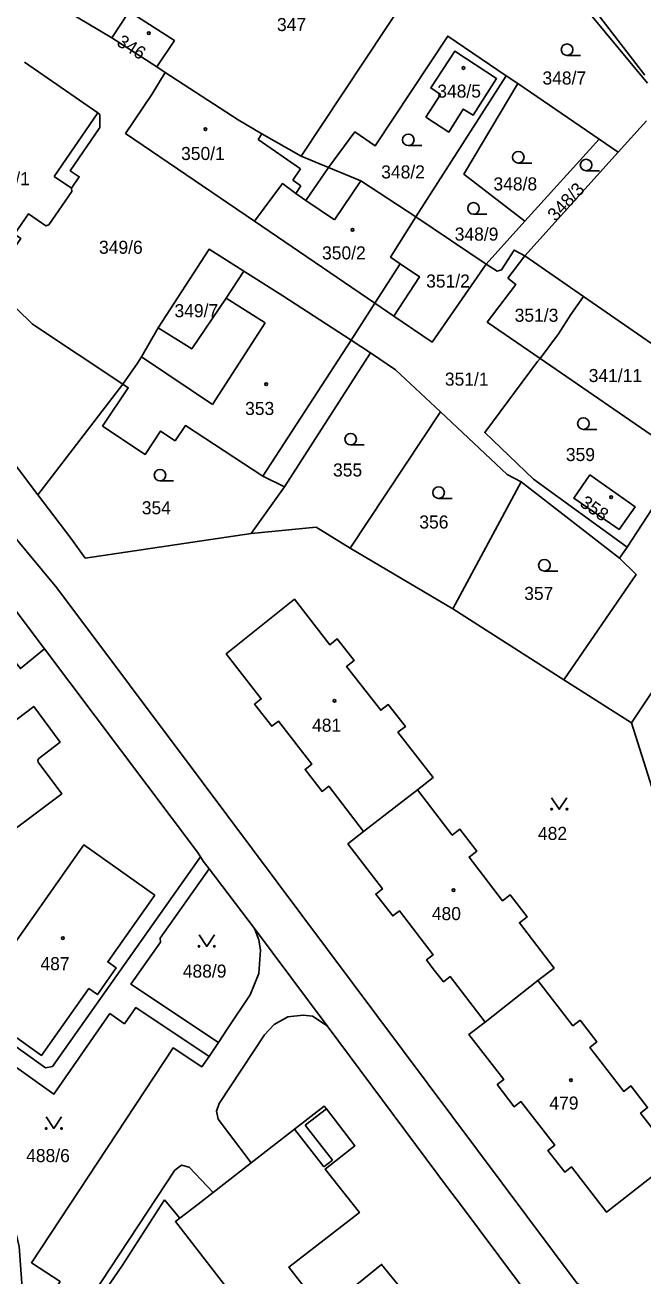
# Model space of a CAD drawing. Extents: x -558358 to -557517, y -1073785 to -1073189.
# Drawn here: x -557990.2 to -557909.7, y -1073433.5 to -1073270.7 of the extents above; entities that cross this region are included whole.
import ezdxf

# ---------------------------------------------------------------- set-up
doc = ezdxf.new("R2010")
doc.units = 0
for name, color, linetype in [('Hranice parcel', 7, 'Continuous'), ('Parcelní čísla', 7, 'Continuous'), ('Vnitřní kresba', 7, 'Continuous'), ('Značky budov', 7, 'Continuous'), ('Značky kultur', 7, 'Continuous')]:
    doc.layers.add(name, color=color, linetype=linetype)

msp = doc.modelspace()

# ---------------------------------------------------------------- linework, layer by layer
at = {"layer": 'Hranice parcel'}
for p, q in [((-557909.08, -1073278.25), (-557930.32, -1073252.64)), ((-557954.2, -1073287.72), (-557935.78, -1073259.94)), ((-557988.45, -1073266.61), (-557978.88, -1073272.32)), ((-557978.88, -1073272.32), (-557973.02, -1073276.12)), ((-557973.02, -1073276.12), (-557971.93, -1073276.83)), ((-557939.28, -1073295.66), (-557927.49, -1073277.3)), ((-557927.49, -1073277.3), (-557926.01, -1073278.28)), ((-557926.01, -1073278.28), (-557915.41, -1073285.51)), ((-557912.91, -1073287.22), (-557909.23, -1073283.14)), ((-557915.41, -1073285.51), (-557925.06, -1073296.21)), ((-557912.91, -1073287.22), (-557915.41, -1073285.51)), ((-557950.63, -1073289.21), (-557954.2, -1073287.72)), ((-557925.08, -1073300.71), (-557912.91, -1073287.22)), ((-557930.1, -1073301.79), (-557939.28, -1073295.66)), ((-557960.27, -1073296.22), (-557944.6, -1073306.89)), ((-557925.06, -1073296.21), (-557930.1, -1073301.79)), ((-557927.31, -1073303.62), (-557925.08, -1073300.71)), ((-557917.44, -1073306), (-557925.08, -1073300.71)), ((-557944.6, -1073306.89), (-557947.68, -1073311.68)), ((-557944.6, -1073306.89), (-557942.12, -1073308.58)), ((-557923.1, -1073314.09), (-557930, -1073309.35)), ((-557945.18, -1073313.34), (-557947.68, -1073311.68)), ((-557956.39, -1073330.78), (-557945.18, -1073313.34)), ((-557923.1, -1073314.09), (-557906.54, -1073325.46)), ((-557988.49, -1073331.84), (-557977.43, -1073317.43)), ((-557947.81, -1073338.78), (-557936.06, -1073321.05)), ((-557911.75, -1073338.65), (-557904.1, -1073326.9)), ((-557960.73, -1073336.87), (-557956.39, -1073330.78)), ((-557934.44, -1073346.66), (-557925.54, -1073330.14)), ((-557912.73, -1073340.1), (-557925.54, -1073330.14)), ((-557911.2, -1073361.51), (-557892.99, -1073334.25)), ((-557947.81, -1073338.78), (-557934.44, -1073346.66)), ((-557911.75, -1073338.65), (-557912.73, -1073340.1)), ((-557934.44, -1073346.66), (-557919.99, -1073355.94)), ((-557919.99, -1073355.94), (-557911.2, -1073361.51)), ((-557911.2, -1073361.51), (-557908.52, -1073369.92)), ((-557939.06, -1073370.25), (-557946.07, -1073375.66)), ((-557967.34, -1073378.97), (-557986.61, -1073406.29)), ((-557972.56, -1073389.56), (-557966.21, -1073380.53)), ((-557966.21, -1073380.53), (-557960.31, -1073388.29)), ((-557960.31, -1073388.29), (-557950.81, -1073400.97)), ((-557960.31, -1073388.29), (-557959.73, -1073389.78)), ((-557923.37, -1073395.09), (-557930.26, -1073400.48)), ((-557950.81, -1073400.97), (-557952.73, -1073399.73)), ((-557966.19, -1073404.96), (-557964.99, -1073403.16)), ((-557965.04, -1073413.14), (-557960.73, -1073418.81)), ((-557965.67, -1073422.67), (-557968.81, -1073419.39)), ((-557960.73, -1073418.81), (-557965.67, -1073422.67)), ((-557970.03, -1073426.04), (-557971.99, -1073423.64))]:
    msp.add_line(p, q, dxfattribs=at)
for points in [[(-557930.24, -1073250.53), (-557916.49, -1073268.06), (-557909.46, -1073277.19)], [(-557973.02, -1073276.12), (-557970.72, -1073272.68), (-557976.62, -1073268.9), (-557978.88, -1073272.32)], [(-557992.18, -1073271.14), (-558017.7, -1073308.66), (-558015.75, -1073309.85), (-558004.08, -1073317.8), (-557996.67, -1073322.48), (-557993.43, -1073325.31), (-557988.49, -1073331.84)], [(-557927.49, -1073277.3), (-557935.12, -1073272.11), (-557944.58, -1073286.41), (-557947.22, -1073284.58), (-557950.63, -1073289.21)], [(-557937.99, -1073282.67), (-557936.08, -1073279.73), (-557937.34, -1073278.85), (-557934.2, -1073274.07), (-557928.77, -1073277.64), (-557931.8, -1073282.4), (-557933.09, -1073281.6), (-557934.98, -1073284.6), (-557937.99, -1073282.67)], [(-557995.47, -1073303.55), (-557992.42, -1073299.14), (-557991.6, -1073299.71), (-557990.74, -1073298.46), (-557991.57, -1073297.9), (-557989.74, -1073295.26), (-557987.45, -1073296.82), (-557987.09, -1073296.7), (-557984.08, -1073292.32), (-557984.13, -1073291.92), (-557983.12, -1073290.42), (-557984.28, -1073289.64), (-557980.42, -1073284.02), (-557980.45, -1073282.32), (-557980.68, -1073282.11), (-557990.25, -1073275.48)], [(-557971.93, -1073276.83), (-557973.65, -1073279.73), (-557977.09, -1073284.77), (-557960.27, -1073296.22)], [(-557971.93, -1073276.83), (-557962.4, -1073283.03), (-557959.33, -1073284.84), (-557954.2, -1073287.72)], [(-557926.01, -1073278.28), (-557933.02, -1073290.08), (-557925.06, -1073296.21)], [(-557960.27, -1073296.22), (-557956.66, -1073291.3), (-557954.92, -1073292.62), (-557953.6, -1073293.52), (-557950.63, -1073289.21)], [(-557950.63, -1073289.21), (-557946.45, -1073290.96), (-557939.28, -1073295.66)], [(-557942.12, -1073308.58), (-557938.8, -1073303.44), (-557941.3, -1073301.76), (-557942.56, -1073300.91), (-557939.28, -1073295.66)], [(-557972.83, -1073310.08), (-557966.21, -1073299.85), (-557961.67, -1073302.72)], [(-557930.1, -1073301.79), (-557928.7, -1073302.72), (-557928.1, -1073302.55), (-557926.47, -1073299.96), (-557925.08, -1073300.71)], [(-557942.12, -1073308.58), (-557937.16, -1073311.96), (-557930.1, -1073301.79)], [(-557977.43, -1073317.43), (-557989.2, -1073309.62), (-557995.47, -1073303.55)], [(-557961.67, -1073302.72), (-557963.96, -1073306.23), (-557968.46, -1073312.83), (-557972.83, -1073310.08)], [(-557947.68, -1073311.68), (-557956.58, -1073305.91), (-557961.67, -1073302.72)], [(-557930, -1073309.35), (-557926.23, -1073304.45), (-557927.31, -1073303.62)], [(-557917.44, -1073306), (-557919.08, -1073308.35), (-557920.7, -1073310.88), (-557923.1, -1073314.09)], [(-557906.54, -1073325.46), (-557900.99, -1073317.38), (-557917.44, -1073306)], [(-557972.83, -1073310.08), (-557975.02, -1073313.87), (-557975.51, -1073314.71), (-557977.43, -1073317.43)], [(-558022.09, -1073311.21), (-558020.08, -1073313.87), (-558000.41, -1073328.2), (-557993.92, -1073334.5), (-557986.04, -1073343.93), (-557967.1, -1073369.2), (-557918.24, -1073434.51), (-557914.64, -1073436.24), (-557909.55, -1073436.22), (-557905.05, -1073434.1), (-557902.57, -1073430.65), (-557891.22, -1073414.37), (-557877.97, -1073395.43)], [(-557936.06, -1073321.05), (-557941.93, -1073315.57), (-557945.18, -1073313.34)], [(-557923.1, -1073314.09), (-557923.42, -1073314.47), (-557930.3, -1073323.72), (-557923.97, -1073329.78), (-557911.75, -1073338.65)], [(-557977.43, -1073317.43), (-557976.74, -1073317.89), (-557980.07, -1073322.91)], [(-557925.54, -1073330.14), (-557927.37, -1073329.18), (-557936.06, -1073321.05)], [(-557980.07, -1073322.91), (-557974.55, -1073326.57), (-557972.53, -1073323.54), (-557970.61, -1073324.82)], [(-557970.61, -1073324.82), (-557969.28, -1073322.81), (-557959.2, -1073329.4), (-557956.39, -1073330.78)], [(-557916.62, -1073329.24), (-557918.71, -1073332.26), (-557912.81, -1073336.33), (-557910.69, -1073333.4), (-557916.62, -1073329.24)], [(-557988.49, -1073331.84), (-557984.2, -1073337.5), (-557982.34, -1073340.07), (-557960.73, -1073336.87)], [(-557960.73, -1073336.87), (-557952.24, -1073336.05), (-557947.81, -1073338.78)], [(-557919.99, -1073355.94), (-557910.58, -1073342.2), (-557912.73, -1073340.1)], [(-557987.64, -1073351.9), (-557990.77, -1073354.47), (-557995.82, -1073348.28), (-557992.92, -1073345.89)], [(-557992.92, -1073345.89), (-557991.47, -1073346.8), (-557987.64, -1073351.9)], [(-557939.06, -1073370.25), (-557937.03, -1073368.65), (-557941.61, -1073362.76), (-557940.64, -1073362.01), (-557942.87, -1073359.14), (-557943.85, -1073359.89), (-557948.29, -1073354.18), (-557947.32, -1073353.42), (-557949.52, -1073350.59), (-557950.49, -1073351.35), (-557955.09, -1073345.44), (-557963.96, -1073352.54), (-557959.4, -1073358.42), (-557960.27, -1073359.1), (-557958.05, -1073361.97), (-557957.18, -1073361.3), (-557952.83, -1073366.91), (-557953.7, -1073367.59), (-557951.48, -1073370.46), (-557950.61, -1073369.79), (-557946.07, -1073375.66)], [(-557987.64, -1073351.9), (-557967.72, -1073378.38), (-557967.34, -1073378.97)], [(-558015.07, -1073378.83), (-558009.7, -1073374.87), (-558009.55, -1073374.62), (-558009.63, -1073374.36), (-558012.72, -1073370.26), (-557996.07, -1073357.8), (-557992.97, -1073361.92), (-557992.74, -1073362.04), (-557992.48, -1073361.98), (-557989.05, -1073359.38), (-557985.61, -1073364.04), (-557988.36, -1073366.15), (-557988.52, -1073366.38), (-557988.48, -1073366.66), (-557985.4, -1073370.76), (-558002.63, -1073383.68), (-558005.71, -1073379.56), (-558005.98, -1073379.48), (-558006.26, -1073379.51), (-558009.96, -1073382.24), (-558012.37, -1073378.99), (-558013.71, -1073380.01)], [(-557923.37, -1073395.09), (-557921.26, -1073393.45), (-557925.78, -1073387.56), (-557924.79, -1073386.8), (-557926.98, -1073383.94), (-557927.98, -1073384.7), (-557932.34, -1073379.01), (-557931.35, -1073378.25), (-557933.54, -1073375.39), (-557934.53, -1073376.15), (-557939.06, -1073370.25)], [(-557946.07, -1073375.66), (-557948.14, -1073377.29), (-557943.62, -1073383.15), (-557944.49, -1073383.82), (-557942.29, -1073386.67), (-557941.42, -1073386), (-557937, -1073391.73), (-557937.87, -1073392.4), (-557937.04, -1073393.49), (-557935.69, -1073395.23), (-557934.82, -1073394.56), (-557930.26, -1073400.48)], [(-557973.25, -1073383.95), (-557982.53, -1073377.43), (-557997.25, -1073398.28), (-557988.03, -1073404.82), (-557981.86, -1073396.11), (-557980.74, -1073396.9), (-557978.29, -1073393.44), (-557979.41, -1073392.65), (-557973.25, -1073383.95)], [(-557967.34, -1073378.97), (-557966.98, -1073379.52), (-557966.21, -1073380.53)], [(-557986.61, -1073406.29), (-557987.5, -1073406.44), (-558001.47, -1073396.48), (-558002.38, -1073393.7), (-558003.7, -1073390.42), (-558005.05, -1073388.34), (-558008.08, -1073385.35), (-558013.71, -1073380.01)], [(-557964.99, -1073403.16), (-557976.4, -1073395.54), (-557972.54, -1073390.07), (-557972.56, -1073389.56)], [(-557959.73, -1073389.78), (-557959.52, -1073391.14), (-557959.72, -1073394.15), (-557960.86, -1073396.95), (-557963.76, -1073401.26), (-557964.99, -1073403.16)], [(-557930.26, -1073400.48), (-557932.35, -1073402.1), (-557927.81, -1073407.96), (-557928.68, -1073408.63), (-557926.46, -1073411.51), (-557925.59, -1073410.83), (-557921.19, -1073416.52), (-557922.06, -1073417.2), (-557919.87, -1073420.02), (-557919, -1073419.35), (-557914.46, -1073425.22), (-557905.47, -1073418.2), (-557910.01, -1073412.34), (-557909.08, -1073411.62), (-557911.27, -1073408.79), (-557912.2, -1073409.51), (-557916.62, -1073403.8), (-557915.7, -1073403.08), (-557917.89, -1073400.24), (-557918.82, -1073400.96), (-557923.37, -1073395.09)], [(-557990.11, -1073441.11), (-557990.95, -1073429.72), (-557991.6, -1073426.99), (-558000.34, -1073399.97), (-557986.42, -1073409.86), (-557979.13, -1073399.38), (-557977.23, -1073400.7), (-557975.75, -1073398.59), (-557966.19, -1073404.96)], [(-557952.73, -1073399.73), (-557953.94, -1073399.59), (-557955.93, -1073399.82), (-557957.72, -1073400.8), (-557958.97, -1073402.15), (-557964.89, -1073411.09), (-557965.23, -1073412.1), (-557965.04, -1073413.14)], [(-557943.74, -1073483.99), (-557922.57, -1073454.37), (-557920.54, -1073448.62), (-557920.67, -1073443.5), (-557923.32, -1073437.76), (-557933.57, -1073424.07), (-557935, -1073422.19), (-557950.81, -1073400.97)], [(-557966.19, -1073404.96), (-557967.15, -1073406.3), (-557970.9, -1073403.86), (-557989.34, -1073431.82), (-557985.62, -1073434.28), (-557990.11, -1073441.11)], [(-557960.73, -1073418.81), (-557955.07, -1073414.41), (-557951.22, -1073411.42), (-557950.93, -1073411.8), (-557947.21, -1073416.59), (-557951.08, -1073419.63), (-557946.63, -1073425.3), (-557955.8, -1073432.39), (-557951.37, -1073438.08), (-557947.44, -1073435.04), (-557943.73, -1073432.04), (-557939.89, -1073436.78), (-557943.7, -1073439.86), (-557943.42, -1073440.21), (-557947.29, -1073443.23), (-557962.81, -1073455.3), (-557971.36, -1073444.52), (-557962.13, -1073437.38), (-557970.6, -1073426.47), (-557970.03, -1073426.04)], [(-557968.81, -1073419.39), (-557969.8, -1073419.14), (-557970.66, -1073419.77), (-557992.19, -1073452.45)], [(-557970.03, -1073426.04), (-557967.63, -1073424.2), (-557965.67, -1073422.67)], [(-557971.99, -1073423.64), (-557977.49, -1073432.15), (-557981.25, -1073437.64), (-557989.89, -1073450.63)]]:
    msp.add_lwpolyline(points, dxfattribs=at)
at = {"layer": 'Vnitřní kresba'}
for p, q in [((-557986.39, -1073290.37), (-557980.68, -1073282.11)), ((-557959.81, -1073285.59), (-557959.33, -1073284.84)), ((-557959.81, -1073285.59), (-557954.3, -1073289.39)), ((-557955.3, -1073290.85), (-557954.3, -1073289.39)), ((-557984.13, -1073291.92), (-557986.39, -1073290.37)), ((-557955.3, -1073290.85), (-557954.25, -1073291.61)), ((-557949.87, -1073296.05), (-557946.45, -1073290.96)), ((-557954.92, -1073292.62), (-557954.25, -1073291.61)), ((-557953.6, -1073293.52), (-557949.87, -1073296.05)), ((-557944.6, -1073306.89), (-557941.3, -1073301.76)), ((-557958.88, -1073309.45), (-557963.96, -1073306.23)), ((-557958.88, -1073309.45), (-557965.78, -1073320.06)), ((-557959.2, -1073329.4), (-557947.68, -1073311.68)), ((-557953.7, -1073413.91), (-557950.93, -1073411.8)), ((-557955.07, -1073414.41), (-557951.25, -1073419.34)), ((-557953.7, -1073413.91), (-557950.12, -1073418.46)), ((-557951.25, -1073419.34), (-557950.12, -1073418.46))]:
    msp.add_line(p, q, dxfattribs=at)
msp.add_lwpolyline([(-557975.02, -1073313.87), (-557968.52, -1073318.2), (-557965.78, -1073320.06)], dxfattribs=at)
at = {"layer": 'Značky budov'}
for centre in [(-557974.06, -1073271.72), (-557933.08, -1073276.26), (-557966.69, -1073284.23), (-557947.51, -1073297.34), (-557958.76, -1073317.44), (-557913.84, -1073332.14), (-557949.87, -1073358.66), (-557934.36, -1073383.3), (-557985.25, -1073389.56), (-557919.07, -1073408.06)]:
    msp.add_circle(centre, 0.175, dxfattribs=at)
at = {"layer": 'Značky kultur'}
for p, q in [((-557919.58, -1073274.62), (-557917.83, -1073274.62)), ((-557940.26, -1073286.37), (-557938.51, -1073286.37)), ((-557925.93, -1073288.63), (-557924.18, -1073288.63)), ((-557917.1, -1073289.64), (-557915.35, -1073289.64)), ((-557931.76, -1073295.29), (-557930.01, -1073295.29)), ((-557917.45, -1073323.31), (-557915.7, -1073323.31)), ((-557947.76, -1073325.33), (-557946.01, -1073325.33)), ((-557972.6, -1073330.02), (-557970.85, -1073330.02)), ((-557936.31, -1073332.3), (-557934.56, -1073332.3)), ((-557922.53, -1073341.76), (-557920.78, -1073341.76))]:
    msp.add_line(p, q, dxfattribs=at)
for points in [[(-557921.59, -1073371.27), (-557920.59, -1073372.77), (-557919.59, -1073371.27)], [(-557967.51, -1073389.13), (-557966.51, -1073390.63), (-557965.51, -1073389.13)], [(-557987.43, -1073412.84), (-557986.43, -1073414.34), (-557985.43, -1073412.84)]]:
    msp.add_lwpolyline(points, dxfattribs=at)
for centre, radius in [((-557919.58, -1073273.87), 0.75), ((-557940.26, -1073285.62), 0.75), ((-557925.93, -1073287.88), 0.75), ((-557917.1, -1073288.89), 0.75), ((-557931.76, -1073294.54), 0.75), ((-557917.45, -1073322.56), 0.75), ((-557947.76, -1073324.58), 0.75), ((-557972.6, -1073329.27), 0.75), ((-557936.31, -1073331.55), 0.75), ((-557922.53, -1073341.01), 0.75), ((-557921.59, -1073372.77), 0.1), ((-557919.59, -1073372.77), 0.1), ((-557967.51, -1073390.63), 0.1), ((-557965.51, -1073390.63), 0.1), ((-557987.43, -1073414.34), 0.1), ((-557985.43, -1073414.34), 0.1)]:
    msp.add_circle(centre, radius, dxfattribs=at)

# ---------------------------------------------------------------- texts
at = {"layer": 'Parcelní čísla'}
for s, p in [('347', (-557957.36, -1073271.45)), ('348/7', (-557922.78, -1073278.41)), ('348/5', (-557936.48, -1073280.12)), ('350/1', (-557969.85, -1073288.24)), ('348/2', (-557943.78, -1073290.64)), ('349/1', (-557995.24, -1073291.52)), ('348/8', (-557929.16, -1073292.2)), ('348/9', (-557934.21, -1073298.74)), ('349/6', (-557980.54, -1073300.45)), ('350/2', (-557951.49, -1073301.18)), ('351/2', (-557937.93, -1073304.85)), ('349/7', (-557970.71, -1073308.71)), ('351/3', (-557926.4, -1073309.3)), ('341/11', (-557916.76, -1073317.15)), ('351/1', (-557935.49, -1073317.62)), ('353', (-557961.51, -1073321.44)), ('359', (-557919.73, -1073327.44)), ('355', (-557950.06, -1073329.45)), ('354', (-557974.97, -1073334.37)), ('356', (-557938.82, -1073336.22)), ('357', (-557925.16, -1073345.52)), ('481', (-557952.79, -1073362.68)), ('482', (-557923.37, -1073376.77)), ('480', (-557937.19, -1073387.21)), ('487', (-557988.17, -1073393.73)), ('488/9', (-557969.63, -1073394.7)), ('479', (-557921.88, -1073411.88)), ('488/6', (-557990.03, -1073418.72))]:
    msp.add_text(s, height=1.7, dxfattribs=at).set_placement(p)
for s, rotation, p in [('346', 328, (-557978.36, -1073273.25)), ('348/3', 47, (-557921.06, -1073296.33)), ('358', 325, (-557918.04, -1073333.2))]:
    msp.add_text(s, height=1.7, rotation=rotation, dxfattribs=at).set_placement(p)

doc.saveas('drawing.dxf')
